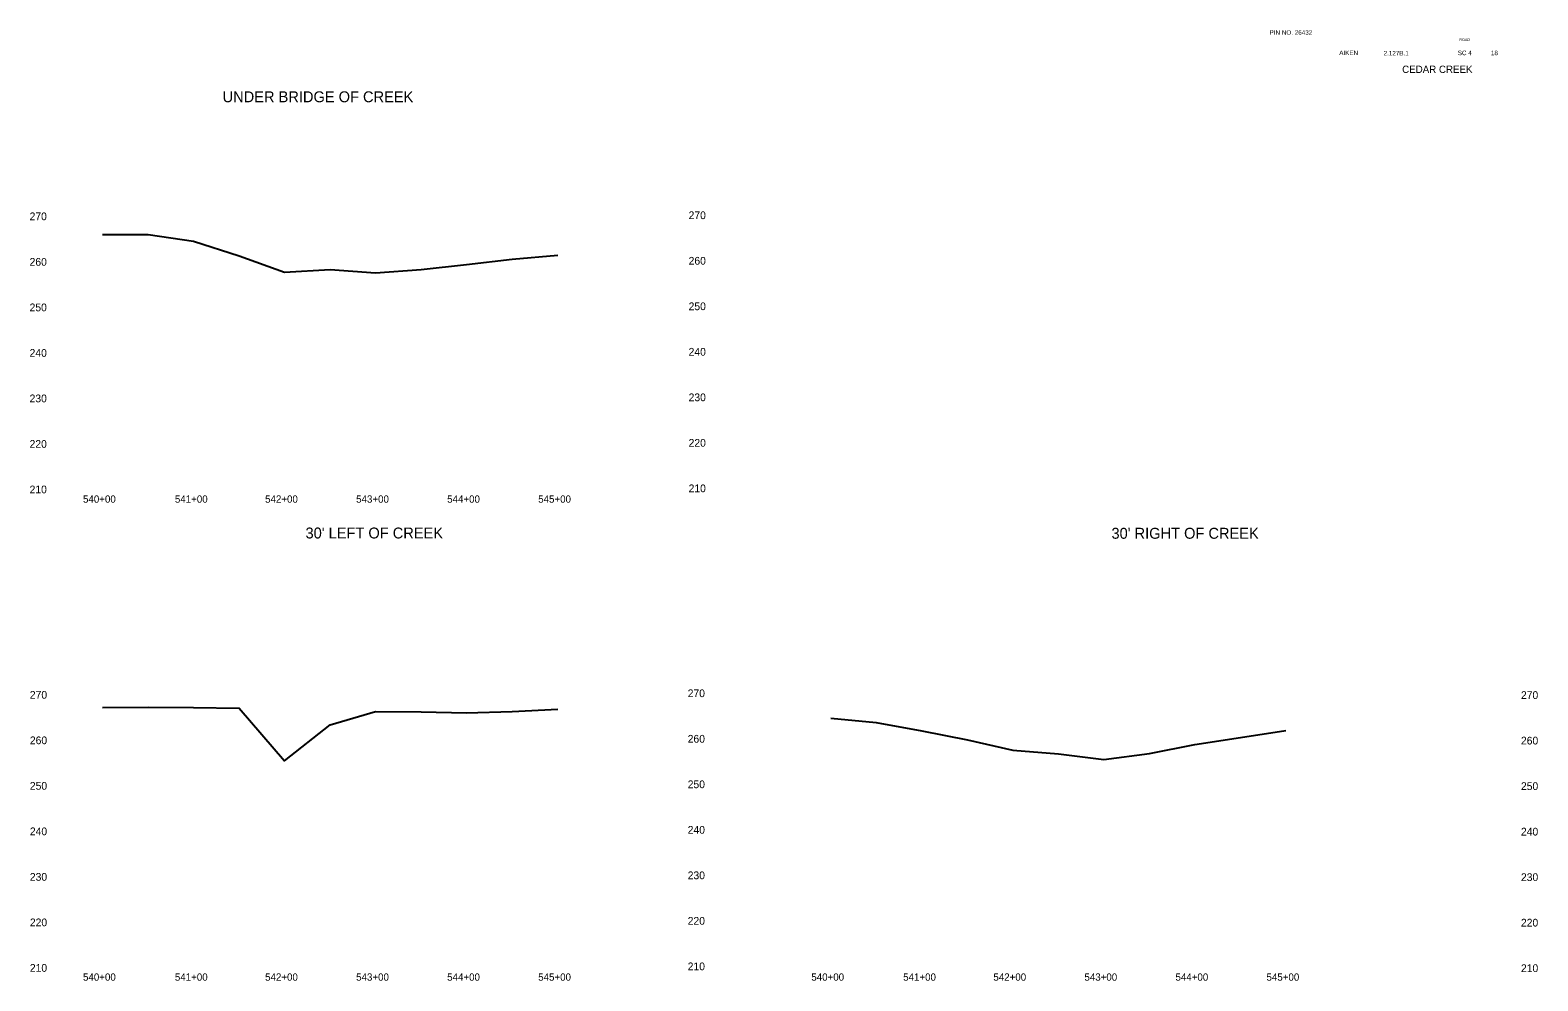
# Model space of a CAD drawing. Extents: x 50163 to 54183, y 54966 to 56011.
# Drawn here: x 52527 to 54183, y 54966 to 56011 of the extents above; entities that cross this region are included whole.
import ezdxf

# ---------------------------------------------------------------- set-up
doc = ezdxf.new("R2010")
doc.units = 0
for name, color, linetype in [('Level 1', 7, 'Continuous'), ('Level 40', 7, 'Continuous'), ('Level 42', 7, 'Continuous'), ('Level 43', 7, 'Continuous')]:
    doc.layers.add(name, color=color, linetype=linetype)

msp = doc.modelspace()

# ---------------------------------------------------------------- linework, layer by layer
at = {"layer": 'Level 40'}
for points in [[(52606.4, 55786.1), (52656.4, 55786.1), (52706.4, 55778.8), (52756.4, 55762.7), (52806.4, 55744.5), (52856.4, 55747.5), (52906.4, 55743.9), (52956.4, 55747.5), (53006.4, 55753.2), (53056.4, 55759.1), (53106.4, 55763.2)], [(52606.4, 55266.6), (52656.4, 55266.8), (52706.4, 55266.5), (52756.4, 55265.7), (52806.4, 55208), (52856.4, 55247.3), (52906.4, 55262.1), (52956.4, 55261.8), (53006.4, 55260.7), (53056.4, 55262.1), (53106.4, 55264.6)], [(53406.4, 55254.7), (53456.4, 55249.8), (53506.4, 55240.7), (53556.4, 55230.8), (53606.4, 55219.7), (53656.4, 55215.6), (53706.4, 55209.2), (53756.4, 55215.9), (53806.4, 55225.6), (53856.4, 55233.4), (53906.4, 55241.2)]]:
    msp.add_lwpolyline(points, dxfattribs=at)

# ---------------------------------------------------------------- texts
at = {"layer": 'Level 1'}
for s, height, p in [('PIN NO. 26432', 5, (53888.4, 56005.4)), ('ROAD', 3, (54096.7, 55998.5)), ('AIKEN', 5, (53964.9, 55983.1)), ('2.127B.1', 5, (54013.6, 55982.7)), ('SC 4', 5, (54095.1, 55983)), ('18', 5, (54131.5, 55983)), ('CEDAR CREEK', 8, (54034, 55963.5))]:
    msp.add_text(s, height=height, dxfattribs=at).set_placement(p)
at = {"layer": 'Level 42'}
for s, height, p in [('270', 8.5, (53250.2, 55802.9)), ('270', 8.5, (52526.3, 55801.7)), ('260', 8.5, (52526.3, 55751.7)), ('260', 8.5, (53250.2, 55752.9)), ('250', 8.5, (52526.3, 55701.7)), ('250', 8.5, (53250.2, 55702.9)), ('240', 8.5, (52526.3, 55651.7)), ('240', 8.5, (53250.2, 55652.9)), ('230', 8.5, (52526.3, 55601.7)), ('230', 8.5, (53250.2, 55602.9)), ('220', 8.5, (52526.3, 55551.7)), ('220', 8.5, (53250.2, 55552.9)), ('210', 8.5, (52526.3, 55501.7)), ('540+00', 8, (52585, 55491.4)), ('541+00', 8, (52685.9, 55491.4)), ('542+00', 8, (52785, 55491.4)), ('543+00', 8, (52885, 55491.4)), ('544+00', 8, (52985, 55491.4)), ('545+00', 8, (53085, 55491.4)), ('210', 8.5, (53250.2, 55502.9)), ('270', 8.5, (52526.6, 55276.1)), ('270', 8.5, (53249.2, 55277.8)), ('270', 8.5, (54164.5, 55275.8)), ('260', 8.5, (52526.6, 55226.1)), ('260', 8.5, (53249.2, 55227.8)), ('260', 8.5, (54164.5, 55225.8)), ('250', 8.5, (52526.6, 55176.1)), ('250', 8.5, (53249.2, 55177.8)), ('250', 8.5, (54164.5, 55175.8)), ('240', 8.5, (52526.6, 55126.1)), ('240', 8.5, (53249.2, 55127.8)), ('240', 8.5, (54164.5, 55125.8)), ('230', 8.5, (52526.6, 55076.1)), ('230', 8.5, (53249.2, 55077.8)), ('230', 8.5, (54164.5, 55075.8)), ('220', 8.5, (52526.6, 55026.1)), ('220', 8.5, (53249.2, 55027.8)), ('220', 8.5, (54164.5, 55025.8)), ('210', 8.5, (52526.6, 54976.1)), ('210', 8.5, (53249.2, 54977.8)), ('210', 8.5, (54164.5, 54975.8)), ('540+00', 8, (52585, 54966.3)), ('541+00', 8, (52685.9, 54966.3)), ('542+00', 8, (52785, 54966.3)), ('543+00', 8, (52885, 54966.3)), ('544+00', 8, (52985, 54966.3)), ('545+00', 8, (53085, 54966.3)), ('540+00', 8, (53385, 54966.3)), ('541+00', 8, (53485.9, 54966.3)), ('542+00', 8, (53585, 54966.3)), ('543+00', 8, (53685, 54966.3)), ('544+00', 8, (53785, 54966.3)), ('545+00', 8, (53885, 54966.3))]:
    msp.add_text(s, height=height, dxfattribs=at).set_placement(p)
at = {"layer": 'Level 43'}
for s, p in [('UNDER BRIDGE OF CREEK', (52738.3, 55931.3)), ("30' LEFT OF CREEK", (52829.4, 55452.1)), ("30' RIGHT OF CREEK", (53714.7, 55451.8))]:
    msp.add_text(s, height=12, dxfattribs=at).set_placement(p)

doc.saveas('drawing.dxf')
